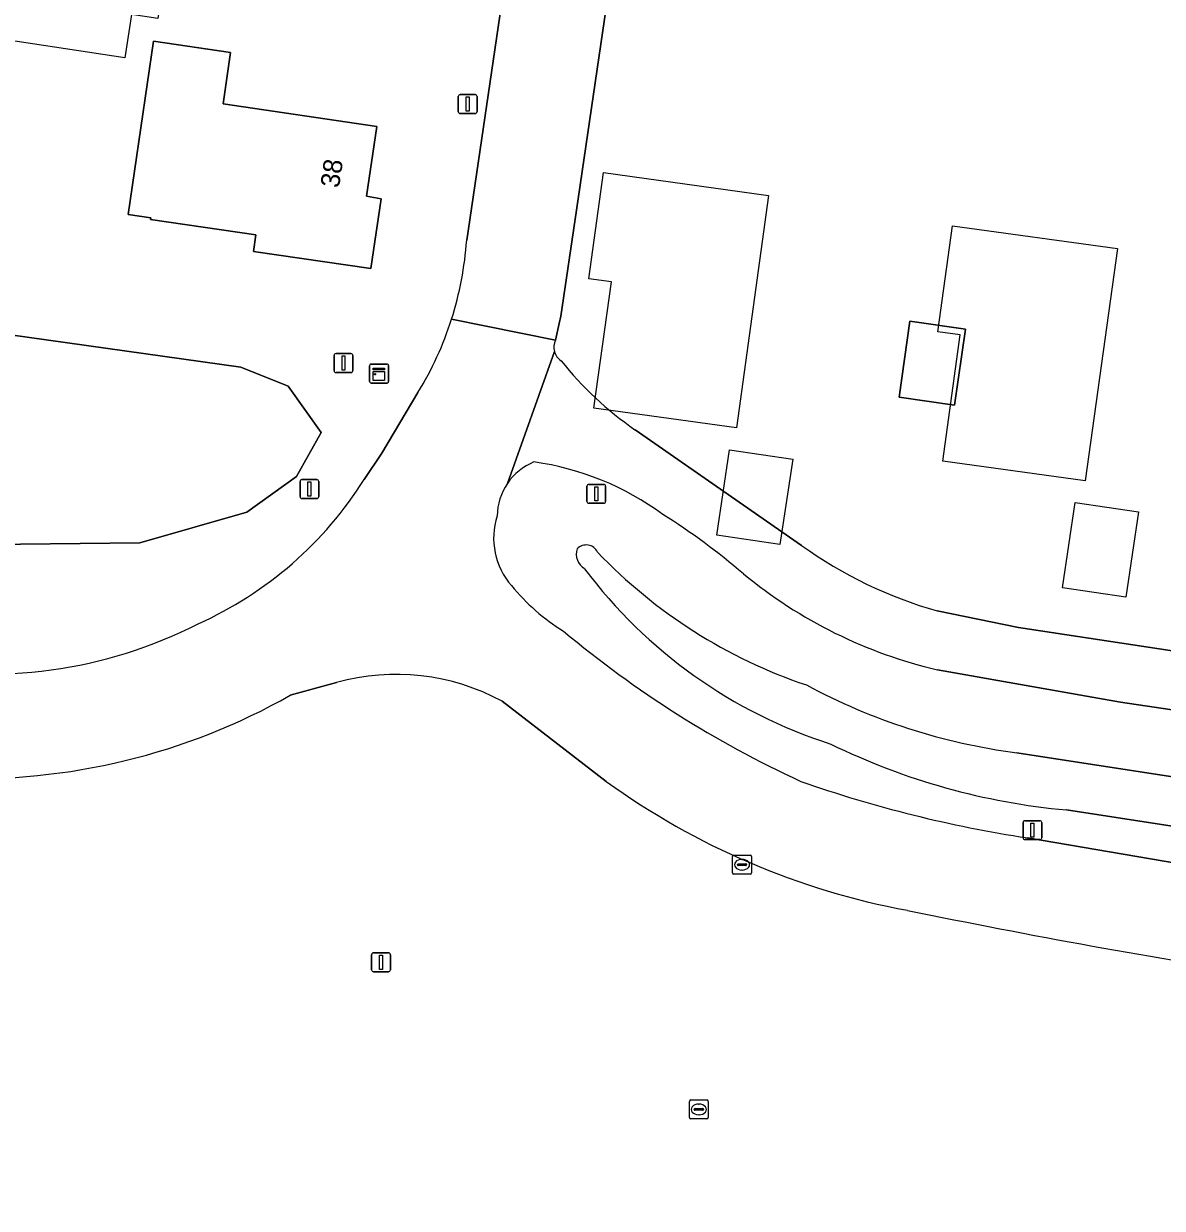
# Model space of a CAD drawing. Extents: x 164148 to 165261, y 382513 to 383432.
# Drawn here: x 164608.6 to 164668.7, y 382807.8 to 382870.3 of the extents above; entities that cross this region are included whole.
import ezdxf

# ---------------------------------------------------------------- set-up
doc = ezdxf.new("R2010")
doc.units = 0
for name, color, linetype in [('IMGEO_Greppel_droge_sloot', 7, 'Continuous'), ('IMGEO_Groenvoorziening', 7, 'Continuous'), ('IMGEO_Kast', 7, 'Continuous'), ('IMGEO_Lichtmast', 7, 'Continuous'), ('IMGEO_Pand', 7, 'Continuous'), ('IMGEO_Pand_nummerreeks', 7, 'Continuous'), ('IMGEO_Pand_vergunning_verleend', 7, 'Continuous'), ('IMGEO_Rijbaan_lokaal_gesloten', 7, 'Continuous'), ('IMGEO_Rioolput', 7, 'Continuous'), ('IMGEO_Verkeersbordpaal', 7, 'Continuous'), ('IMGEO_Waterloop', 7, 'Continuous')]:
    doc.layers.add(name, color=color, linetype=linetype)

msp = doc.modelspace()

# ---------------------------------------------------------------- linework, layer by layer
at = {"layer": 'IMGEO_Greppel_droge_sloot'}
msp.add_lwpolyline([(164622.522, 382851.143), (164620.019, 382852.143), (164587.426, 382856.719), (164586.109, 382855.237), (164586.022, 382853.577), (164585.816, 382849.638), (164586.208, 382848.245), (164597.626, 382845.705), (164605.228, 382842.766), (164614.682, 382842.88), (164620.345, 382844.505), (164622.967, 382846.386), (164624.265, 382848.709)], close=True, dxfattribs=at)
at = {"layer": 'IMGEO_Groenvoorziening'}
for points in [[(164852.653, 382976.484), (164848.685, 382977.103), (164764.64, 382989.85), (164659.275, 383005.882), (164658.504, 383000.69), (164650.933, 382950.305), (164641.67, 382887.255), (164640.801, 382881.34), (164637.731, 382860.442), (164636.909, 382854.849), (164636.824, 382854.453), (164636.636, 382853.576)], [(164631.941, 382858.849), (164645.496, 382950.967)], [(164626.525, 382846.214), (164627.467, 382847.605), (164629.371, 382850.812)], [(164640.825, 382848.85), (164649.619, 382842.734)], [(164656.77, 382839.283), (164661.062, 382838.413), (164733.461, 382827.436)], [(164697.492, 382829.863), (164666.441, 382834.462), (164656.796, 382836.171)], [(164625.075, 382835.509), (164622.633, 382834.832)], [(164639.309, 382830.29), (164633.815, 382834.514)], [(164660.986, 382831.801), (164745.457, 382818.79)], [(164733.826, 382817.819), (164706.001, 382822.248), (164663.604, 382828.783)], [(164661.544, 382827.31), (164676.075, 382824.823), (164691.502, 382822.526), (164754.951, 382813.578), (164760.72, 382813.009), (164760.711, 382813.543)]]:
    msp.add_lwpolyline(points, dxfattribs=at)
for points in [[(164615.414, 382869.359), (164619.482, 382868.754), (164619.08, 382866.049), (164627.197, 382864.846), (164626.657, 382861.165), (164627.423, 382861.038), (164626.879, 382857.35), (164620.687, 382858.256), (164620.815, 382859.132), (164615.254, 382859.943), (164615.267, 382860.032), (164614.076, 382860.206)], [(164587.426, 382856.719), (164620.019, 382852.143), (164622.522, 382851.143), (164624.265, 382848.709), (164622.967, 382846.386), (164620.345, 382844.505), (164614.682, 382842.88), (164605.228, 382842.766), (164597.626, 382845.705), (164586.208, 382848.245), (164585.816, 382849.638), (164586.022, 382853.577), (164586.109, 382855.237)], [(164657.686, 382850.138), (164654.762, 382850.56), (164655.336, 382854.579), (164658.266, 382854.156)]]:
    msp.add_lwpolyline(points, close=True, dxfattribs=at)
for centre, radius, start, end in [((164614.251, 382860.072), 17.732, 342.28102, 356.0457), ((164614.308, 382860.055), 17.673, 328.46547, 342.27616), ((164637.382, 382853.189), 0.841, 152.60921, 194.62643), ((164637.376, 382853.189), 0.835, 194.73586, 237.02514), ((164651.102, 382863.785), 18.13, 218.5418, 235.46772), ((164636.649, 382844.278), 3.092, 111.95918, 145.82739), ((164633.379, 382832.203), 15.091, 53.78982, 81.94655), ((164609.633, 382856.825), 19.948, 311.0819, 327.86283), ((164636.658, 382844.27), 3.104, 145.78823, 179.5151), ((164637.145, 382843.116), 3.78, 161.80672, 221.36383), ((164622.528, 382813.112), 36.992, 49.51315, 57.7016), ((164638.251, 382842.105), 0.661, 25.83535, 136.14256), ((164663.285, 382861.917), 23.553, 234.53445, 253.94258), ((164638.604, 382842.276), 0.878, 160.91025, 240.00999), ((164658.547, 382861.178), 27.222, 223.63721, 251.41031), ((164609.592, 382856.866), 20.006, 294.15036, 311.09468), ((164659.142, 382857.216), 26.203, 216.8143, 252.24983), ((164662.554, 382860.69), 25.186, 230.53472, 256.78323), ((164642.839, 382847.616), 11.034, 219.36306, 238.36276), ((164606.726, 382860.238), 24.287, 258.47197, 297.0664), ((164672.963, 382881.07), 55.907, 230.03333, 245.27091), ((164628.214, 382824.197), 11.74, 61.50287, 105.50745), ((164665.145, 382863.799), 32.267, 241.74289, 262.59431), ((164605.926, 382864.337), 33.907, 267.73441, 299.5194), ((164666.796, 382864.232), 35.593, 243.92946, 264.85434), ((164662.342, 382862.128), 39.296, 234.11688, 259.54943), ((164671.384, 382892.357), 65.787, 250.6399, 261.39802), ((164737.185, 383221.214), 406.09, 258.35464, 261.15794)]:
    msp.add_arc(centre, radius, start, end, dxfattribs=at)
at = {"layer": 'IMGEO_Kast'}
for p, q in [((164626.817, 382851.387), (164626.817, 382852.228)), ((164626.817, 382852.228), (164626.817, 382851.387)), ((164626.892, 382852.312), (164627.733, 382852.312)), ((164627.733, 382852.312), (164626.892, 382852.312)), ((164627.817, 382852.237), (164627.817, 382851.396)), ((164627.817, 382851.396), (164627.817, 382852.237)), ((164627.742, 382851.312), (164626.901, 382851.312)), ((164626.901, 382851.312), (164627.742, 382851.312))]:
    msp.add_line(p, q, dxfattribs=at)
for points in [[(164627.012, 382852.102), (164627.612, 382852.102), (164627.612, 382852.017), (164627.012, 382852.017), (164627.012, 382852.102)], [(164627.012, 382851.927), (164627.612, 382851.927), (164627.612, 382851.438), (164627.012, 382851.438), (164627.012, 382851.927)]]:
    msp.add_lwpolyline(points, dxfattribs=at)
msp.add_circle((164627.096, 382851.776), 0.0377, dxfattribs=at)
for centre, start, end in [((164626.895, 382852.234), 92.4484, 184.28452), ((164626.895, 382852.234), 92.4484, 184.28452), ((164627.739, 382852.234), 2.4484, 94.28452), ((164627.739, 382852.234), 2.4484, 94.28452), ((164626.895, 382851.39), 182.4484, 274.28452), ((164626.895, 382851.39), 182.4484, 274.28452), ((164627.739, 382851.39), 272.4484, 4.28452), ((164627.739, 382851.39), 272.4484, 4.28452)]:
    msp.add_arc(centre, 0.0779, start, end, dxfattribs=at)
at = {"layer": 'IMGEO_Lichtmast'}
for p, q in [((164623.145, 382845.318), (164623.145, 382846.118)), ((164623.145, 382846.118), (164623.145, 382845.318)), ((164623.245, 382846.218), (164624.035, 382846.218)), ((164624.035, 382846.218), (164623.245, 382846.218)), ((164624.135, 382846.118), (164624.135, 382845.318)), ((164624.135, 382845.318), (164624.135, 382846.118)), ((164624.035, 382845.218), (164623.245, 382845.218)), ((164623.245, 382845.218), (164624.035, 382845.218)), ((164661.305, 382827.315), (164661.305, 382828.115)), ((164661.305, 382828.115), (164661.305, 382827.315)), ((164661.405, 382828.215), (164662.195, 382828.215)), ((164662.195, 382828.215), (164661.405, 382828.215)), ((164662.295, 382828.115), (164662.295, 382827.315)), ((164662.295, 382827.315), (164662.295, 382828.115)), ((164662.195, 382827.215), (164661.405, 382827.215)), ((164661.405, 382827.215), (164662.195, 382827.215)), ((164626.926, 382820.341), (164626.926, 382821.141)), ((164626.926, 382821.141), (164626.926, 382820.341)), ((164627.026, 382821.241), (164627.816, 382821.241)), ((164627.816, 382821.241), (164627.026, 382821.241)), ((164627.916, 382821.141), (164627.916, 382820.341)), ((164627.916, 382820.341), (164627.916, 382821.141)), ((164627.816, 382820.241), (164627.026, 382820.241)), ((164627.026, 382820.241), (164627.816, 382820.241))]:
    msp.add_line(p, q, dxfattribs=at)
for points in [[(164623.565, 382846.093), (164623.715, 382846.093), (164623.715, 382845.343), (164623.565, 382845.343), (164623.565, 382846.093)], [(164661.725, 382828.09), (164661.875, 382828.09), (164661.875, 382827.34), (164661.725, 382827.34), (164661.725, 382828.09)], [(164627.346, 382821.116), (164627.496, 382821.116), (164627.496, 382820.366), (164627.346, 382820.366), (164627.346, 382821.116)]]:
    msp.add_lwpolyline(points, dxfattribs=at)
for centre, start, end in [((164623.245, 382846.118), 90, 180), ((164623.245, 382846.118), 90, 180), ((164624.035, 382846.118), 0, 90), ((164624.035, 382846.118), 360, 90), ((164623.245, 382845.318), 180, 270), ((164623.245, 382845.318), 180, 270), ((164624.035, 382845.318), 270, 0), ((164624.035, 382845.318), 270, 0), ((164661.405, 382828.115), 90, 180), ((164661.405, 382828.115), 90, 180), ((164662.195, 382828.115), 0, 90), ((164662.195, 382828.115), 360, 90), ((164661.405, 382827.315), 180, 270), ((164661.405, 382827.315), 180, 270), ((164662.195, 382827.315), 270, 0), ((164662.195, 382827.315), 270, 0), ((164627.026, 382821.141), 90, 180), ((164627.026, 382821.141), 90, 180), ((164627.816, 382821.141), 0, 90), ((164627.816, 382821.141), 360, 90), ((164627.026, 382820.341), 180, 270), ((164627.026, 382820.341), 180, 270), ((164627.816, 382820.341), 270, 0), ((164627.816, 382820.341), 270, 0)]:
    msp.add_arc(centre, 0.1, start, end, dxfattribs=at)
at = {"layer": 'IMGEO_Pand'}
for points in [[(164627.197, 382864.846), (164619.08, 382866.049), (164619.482, 382868.754), (164615.414, 382869.359), (164614.076, 382860.206), (164615.267, 382860.032), (164615.254, 382859.943), (164620.815, 382859.132), (164620.687, 382858.256), (164626.879, 382857.35), (164627.423, 382861.038), (164626.657, 382861.165)], [(164655.336, 382854.579), (164654.762, 382850.56), (164657.686, 382850.138), (164658.266, 382854.156)]]:
    msp.add_lwpolyline(points, close=True, dxfattribs=at)
at = {"layer": 'IMGEO_Pand_vergunning_verleend'}
for points in [[(164601.361, 382870.371), (164602.424, 382877.397), (164616.358, 382875.289), (164615.642, 382870.555), (164614.242, 382870.766), (164613.895, 382868.476)], [(164638.396, 382856.819), (164639.17, 382862.421), (164647.879, 382861.217), (164646.184, 382848.95), (164638.659, 382849.99), (164639.581, 382856.655)], [(164656.8, 382854.014), (164657.575, 382859.616), (164666.284, 382858.412), (164664.588, 382846.145), (164657.064, 382847.185), (164657.985, 382853.85)], [(164645.141, 382843.279), (164645.812, 382847.786), (164649.147, 382847.289), (164648.476, 382842.783)], [(164663.391, 382840.506), (164664.062, 382845.013), (164667.397, 382844.516), (164666.726, 382840.01)]]:
    msp.add_lwpolyline(points, close=True, dxfattribs=at)
at = {"layer": 'IMGEO_Rijbaan_lokaal_gesloten'}
for points in [[(164650.933, 382950.305), (164658.504, 383000.69), (164653.078, 383001.462), (164651.902, 382993.63), (164651.008, 382987.673), (164645.496, 382950.967), (164631.941, 382858.849)], [(164631.142, 382854.675), (164636.636, 382853.576), (164636.824, 382854.453), (164636.909, 382854.849), (164637.731, 382860.442), (164640.801, 382881.34), (164641.67, 382887.255), (164650.933, 382950.305)], [(164636.636, 382853.576), (164631.142, 382854.675)], [(164636.569, 382852.977), (164634.091, 382846.015)], [(164634.091, 382846.015), (164636.569, 382852.977)], [(164629.371, 382850.812), (164627.467, 382847.605), (164626.525, 382846.214)], [(164649.619, 382842.734), (164640.825, 382848.85)], [(164661.062, 382838.413), (164656.77, 382839.283)], [(164733.461, 382827.436), (164661.062, 382838.413)], [(164656.796, 382836.171), (164666.441, 382834.462), (164697.492, 382829.863), (164736.452, 382823.896)], [(164622.633, 382834.832), (164625.075, 382835.509)], [(164633.815, 382834.514), (164639.309, 382830.29)], [(164766.188, 382806.256), (164787.963, 382802.851), (164789.36, 382802.852), (164789.654, 382802.818), (164790.597, 382807.739), (164790.123, 382807.809), (164775.709, 382810.036), (164760.72, 382813.009), (164754.951, 382813.578), (164691.502, 382822.526), (164676.075, 382824.823), (164661.544, 382827.31)]]:
    msp.add_lwpolyline(points, dxfattribs=at)
for centre, radius, start, end in [((164614.251, 382860.072), 17.732, 342.28102, 356.0457), ((164614.308, 382860.055), 17.673, 328.46547, 342.27616), ((164637.382, 382853.189), 0.841, 152.60921, 194.62643), ((164637.376, 382853.189), 0.835, 194.73586, 237.02514), ((164651.102, 382863.785), 18.13, 218.5418, 235.46772), ((164636.649, 382844.278), 3.092, 111.95918, 145.82739), ((164633.379, 382832.203), 15.091, 53.78982, 81.94655), ((164609.633, 382856.825), 19.948, 311.0819, 327.86283), ((164636.658, 382844.27), 3.104, 145.78823, 179.5151), ((164637.145, 382843.116), 3.78, 161.80672, 221.36383), ((164622.528, 382813.112), 36.992, 49.51315, 57.7016), ((164663.285, 382861.917), 23.553, 234.53445, 253.94258), ((164609.592, 382856.866), 20.006, 294.15036, 311.09468), ((164662.554, 382860.69), 25.186, 230.53472, 256.78323), ((164642.839, 382847.616), 11.034, 219.36306, 238.36276), ((164606.726, 382860.238), 24.287, 258.47197, 297.0664), ((164672.963, 382881.07), 55.907, 230.03333, 245.27091), ((164628.214, 382824.197), 11.74, 61.50287, 105.50745), ((164605.926, 382864.337), 33.907, 267.73441, 299.5194), ((164662.342, 382862.128), 39.296, 234.11688, 259.54943), ((164671.384, 382892.357), 65.787, 250.6399, 261.39802), ((164737.185, 383221.214), 406.09, 258.35464, 261.15794)]:
    msp.add_arc(centre, radius, start, end, dxfattribs=at)
at = {"layer": 'IMGEO_Rioolput'}
for p, q in [((164645.974, 382825.465), (164645.974, 382826.317)), ((164646.049, 382826.391), (164646.901, 382826.391)), ((164646.233, 382825.885), (164646.233, 382825.897)), ((164646.671, 382825.848), (164646.273, 382825.848)), ((164646.276, 382825.934), (164646.674, 382825.934)), ((164646.462, 382826.171), (164646.487, 382826.171)), ((164646.717, 382825.897), (164646.717, 382825.885)), ((164646.975, 382826.317), (164646.975, 382825.465)), ((164646.901, 382825.391), (164646.049, 382825.391)), ((164646.485, 382825.611), (164646.46, 382825.611)), ((164643.693, 382812.551), (164643.693, 382813.403)), ((164643.768, 382813.477), (164644.62, 382813.477)), ((164644.694, 382813.403), (164644.694, 382812.551)), ((164643.952, 382812.971), (164643.952, 382812.983)), ((164644.39, 382812.934), (164643.992, 382812.934)), ((164643.995, 382813.02), (164644.393, 382813.02)), ((164644.204, 382812.697), (164644.179, 382812.697)), ((164644.181, 382813.257), (164644.206, 382813.257)), ((164644.436, 382812.983), (164644.436, 382812.971)), ((164644.62, 382812.477), (164643.768, 382812.477))]:
    msp.add_line(p, q, dxfattribs=at)
for points in [[(164645.974, 382825.465), (164645.974, 382826.317)], [(164646.049, 382826.391), (164646.901, 382826.391)], [(164646.975, 382826.317), (164646.975, 382825.465)], [(164646.901, 382825.391), (164646.049, 382825.391)], [(164643.693, 382812.551), (164643.693, 382813.403)], [(164643.768, 382813.477), (164644.62, 382813.477)], [(164644.694, 382813.403), (164644.694, 382812.551)], [(164644.62, 382812.477), (164643.768, 382812.477)]]:
    msp.add_lwpolyline(points, dxfattribs=at)
for centre, radius, start, end in [((164646.051, 382826.315), 0.0765, 91.55205, 178.44795), ((164646.051, 382826.315), 0.0765, 91.55205, 178.44795), ((164646.273, 382825.894), 0.0403, 85.87752, 175.75265), ((164646.27, 382825.884), 0.0366, 178.93798, 274.71019), ((164646.674, 382825.891), 0.043, 264.86636, 352.45326), ((164646.678, 382825.896), 0.0386, 1.73085, 96.63898), ((164646.899, 382826.315), 0.0765, 1.55205, 88.44795), ((164646.899, 382826.315), 0.0765, 1.55205, 88.44795), ((164646.051, 382825.467), 0.0765, 181.55205, 268.44795), ((164646.051, 382825.467), 0.0765, 181.55205, 268.44795), ((164646.899, 382825.467), 0.0765, 271.55205, 358.44795), ((164646.899, 382825.467), 0.0765, 271.55205, 358.44795), ((164643.77, 382813.401), 0.0765, 91.55205, 178.44795), ((164643.77, 382813.401), 0.0765, 91.55205, 178.44795), ((164644.618, 382813.401), 0.0765, 1.55205, 88.44795), ((164644.618, 382813.401), 0.0765, 1.55205, 88.44795), ((164643.992, 382812.98), 0.0403, 85.87752, 175.75265), ((164643.989, 382812.97), 0.0366, 178.93798, 274.71019), ((164644.393, 382812.977), 0.043, 264.86636, 352.45326), ((164644.397, 382812.982), 0.0386, 1.73085, 96.63898), ((164643.77, 382812.553), 0.0765, 181.55205, 268.44795), ((164643.77, 382812.553), 0.0765, 181.55205, 268.44795), ((164644.618, 382812.553), 0.0765, 271.55205, 358.44795), ((164644.618, 382812.553), 0.0765, 271.55205, 358.44795)]:
    msp.add_arc(centre, radius, start, end, dxfattribs=at)
for centre, major_axis, ratio, start_param, end_param in [((164646.461, 382825.891), (-0.387, 0.002), 0.722429, 4.712389, 7.853982), ((164646.486, 382825.891), (-0.39, 0.002), 0.717154, 1.570796, 4.712389), ((164644.18, 382812.977), (-0.387, 0.002), 0.722429, 4.712389, 7.853982), ((164644.205, 382812.977), (-0.39, 0.002), 0.717154, 1.570796, 4.712389)]:
    msp.add_ellipse(centre, major_axis=major_axis, ratio=ratio, start_param=start_param, end_param=end_param, dxfattribs=at)
at = {"layer": 'IMGEO_Verkeersbordpaal'}
for p, q in [((164631.499, 382865.634), (164631.499, 382866.434)), ((164631.499, 382866.434), (164631.499, 382865.634)), ((164631.599, 382866.534), (164632.389, 382866.534)), ((164632.389, 382866.534), (164631.599, 382866.534)), ((164632.489, 382866.434), (164632.489, 382865.634)), ((164632.489, 382865.634), (164632.489, 382866.434)), ((164632.389, 382865.534), (164631.599, 382865.534)), ((164631.599, 382865.534), (164632.389, 382865.534)), ((164624.944, 382851.965), (164624.944, 382852.765)), ((164624.944, 382852.765), (164624.944, 382851.965)), ((164625.044, 382852.865), (164625.834, 382852.865)), ((164625.834, 382852.865), (164625.044, 382852.865)), ((164625.934, 382852.765), (164625.934, 382851.965)), ((164625.934, 382851.965), (164625.934, 382852.765)), ((164625.834, 382851.865), (164625.044, 382851.865)), ((164625.044, 382851.865), (164625.834, 382851.865)), ((164638.285, 382845.063), (164638.285, 382845.863)), ((164638.285, 382845.863), (164638.285, 382845.063)), ((164638.385, 382845.963), (164639.175, 382845.963)), ((164639.175, 382845.963), (164638.385, 382845.963)), ((164639.275, 382845.863), (164639.275, 382845.063)), ((164639.275, 382845.063), (164639.275, 382845.863)), ((164639.175, 382844.963), (164638.385, 382844.963)), ((164638.385, 382844.963), (164639.175, 382844.963))]:
    msp.add_line(p, q, dxfattribs=at)
for points in [[(164631.919, 382866.409), (164632.069, 382866.409), (164632.069, 382865.659), (164631.919, 382865.659), (164631.919, 382866.409)], [(164625.364, 382852.74), (164625.514, 382852.74), (164625.514, 382851.99), (164625.364, 382851.99), (164625.364, 382852.74)], [(164638.705, 382845.838), (164638.855, 382845.838), (164638.855, 382845.088), (164638.705, 382845.088), (164638.705, 382845.838)]]:
    msp.add_lwpolyline(points, dxfattribs=at)
for centre, start, end in [((164631.599, 382866.434), 90, 180), ((164631.599, 382866.434), 90, 180), ((164632.389, 382866.434), 0, 90), ((164632.389, 382866.434), 360, 90), ((164631.599, 382865.634), 180, 270), ((164631.599, 382865.634), 180, 270), ((164632.389, 382865.634), 270, 0), ((164632.389, 382865.634), 270, 0), ((164625.044, 382852.765), 90, 180), ((164625.044, 382852.765), 90, 180), ((164625.834, 382852.765), 0, 90), ((164625.834, 382852.765), 360, 90), ((164625.044, 382851.965), 180, 270), ((164625.044, 382851.965), 180, 270), ((164625.834, 382851.965), 270, 0), ((164625.834, 382851.965), 270, 0), ((164638.385, 382845.863), 90, 180), ((164638.385, 382845.863), 90, 180), ((164639.175, 382845.863), 0, 90), ((164639.175, 382845.863), 360, 90), ((164638.385, 382845.063), 180, 270), ((164638.385, 382845.063), 180, 270), ((164639.175, 382845.063), 270, 0), ((164639.175, 382845.063), 270, 0)]:
    msp.add_arc(centre, 0.1, start, end, dxfattribs=at)
at = {"layer": 'IMGEO_Waterloop'}
for points in [[(164745.457, 382818.79), (164660.986, 382831.801)], [(164663.604, 382828.783), (164706.001, 382822.248), (164733.826, 382817.819)]]:
    msp.add_lwpolyline(points, dxfattribs=at)
for centre, radius, start, end in [((164638.251, 382842.105), 0.661, 25.83535, 136.14256), ((164638.604, 382842.276), 0.878, 160.91025, 240.00999), ((164658.547, 382861.178), 27.222, 223.63721, 251.41031), ((164659.142, 382857.216), 26.203, 216.8143, 252.24983), ((164665.145, 382863.799), 32.267, 241.74289, 262.59431), ((164666.796, 382864.232), 35.593, 243.92946, 264.85434)]:
    msp.add_arc(centre, radius, start, end, dxfattribs=at)

# ---------------------------------------------------------------- texts
at = {"layer": 'IMGEO_Pand_nummerreeks'}
msp.add_text('38', height=1, rotation=81.65222, dxfattribs=at).set_placement((164625.202, 382861.577))

doc.saveas('drawing.dxf')
